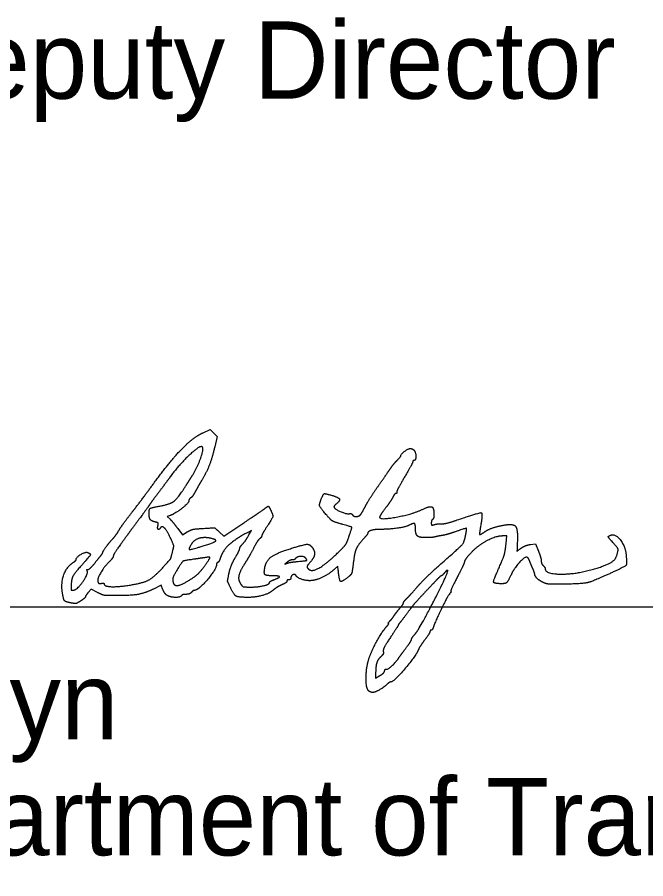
# Model space of a CAD drawing. Extents: x 0 to 34, y 0 to 22.
# Drawn here: x 25.68 to 26.819, y 7.064 to 8.624 of the extents above; entities that cross this region are included whole.
import ezdxf

# ---------------------------------------------------------------- set-up
doc = ezdxf.new("R2010")
doc.units = 0
for name, color, linetype in [('Default', 7, 'Continuous'), ('SH_Data', 7, 'Continuous'), ('SH_Text', 7, 'Continuous')]:
    doc.layers.add(name, color=color, linetype=linetype)

msp = doc.modelspace()

# ---------------------------------------------------------------- linework, layer by layer
at = {"layer": 'Default'}
for points in [[(26.0172, 7.8718), (26.0299, 7.8777), (26.0362, 7.8713), (26.0426, 7.865), (26.0382, 7.8463)], [(25.9573, 7.7219), (25.9523, 7.7203), (25.9575, 7.7151)], [(26.0463, 7.6922), (26.0544, 7.6846), (26.0907, 7.7087)], [(25.9711, 7.6985), (25.9797, 7.687), (25.9885, 7.6922)], [(26.1002, 7.6869), (26.1046, 7.6949), (26.0991, 7.6919)], [(26.566, 7.671), (26.5675, 7.6848), (26.5597, 7.6848)], [(26.6099, 7.6694), (26.6195, 7.6709), (26.6246, 7.6574)], [(26.2619, 7.6232), (26.2613, 7.63), (26.2554, 7.6249)], [(25.9443, 7.5876), (25.941, 7.5956), (25.9271, 7.5888)], [(25.8257, 7.5826), (25.8142, 7.5884), (25.8091, 7.5826)], [(26.3297, 7.4371), (26.3297, 7.4277), (26.3372, 7.4321)]]:
    msp.add_lwpolyline(points, dxfattribs=at)
for points in [[(25.9277, 7.78), (25.9574, 7.8206), (25.9992, 7.8635), (26.0172, 7.8718)], [(26.0158, 7.846), (26.0121, 7.8497), (25.9736, 7.814), (25.9582, 7.7927)], [(25.9975, 7.794), (26.0069, 7.8089), (26.0189, 7.8429), (26.0158, 7.846)], [(26.0382, 7.8463), (26.0332, 7.8251), (26.024, 7.8015), (26.0146, 7.7856)], [(26.3753, 7.8299), (26.3753, 7.8327), (26.3885, 7.843), (26.3922, 7.8431)], [(26.3922, 7.8431), (26.3942, 7.8432), (26.3972, 7.8419), (26.3988, 7.8403)], [(26.3687, 7.8218), (26.3723, 7.8254), (26.3753, 7.8291), (26.3753, 7.8299)], [(26.3988, 7.8403), (26.4023, 7.8368), (26.4027, 7.8216), (26.3993, 7.8216)], [(26.3549, 7.8046), (26.3588, 7.8104), (26.3651, 7.8182), (26.3687, 7.8218)], [(26.3969, 7.8191), (26.3969, 7.8177), (26.3904, 7.8056), (26.3825, 7.7922)], [(26.3993, 7.8216), (26.398, 7.8216), (26.3969, 7.8205), (26.3969, 7.8191)], [(26.3333, 7.7736), (26.3412, 7.7848), (26.3509, 7.7988), (26.3549, 7.8046)], [(25.9582, 7.7927), (25.9546, 7.7877), (25.9452, 7.7751), (25.9373, 7.7646)], [(25.987, 7.7773), (25.9902, 7.7825), (25.995, 7.79), (25.9975, 7.794)], [(26.0146, 7.7856), (26.0111, 7.7797), (26.0059, 7.7705), (26.003, 7.7652)], [(26.3825, 7.7922), (26.3746, 7.7788), (26.3681, 7.7664), (26.3681, 7.7647)], [(25.8875, 7.7265), (25.8964, 7.7379), (25.9145, 7.7619), (25.9277, 7.78)], [(25.9372, 7.7387), (25.9578, 7.7424), (25.9718, 7.7533), (25.987, 7.7773)], [(26.003, 7.7652), (26.0002, 7.7599), (25.9964, 7.7547), (25.9946, 7.7537)], [(26.3119, 7.74), (26.3157, 7.7473), (26.3253, 7.7624), (26.3333, 7.7736)], [(25.9373, 7.7646), (25.9294, 7.7541), (25.9213, 7.7431), (25.9193, 7.7401)], [(25.9946, 7.7537), (25.9928, 7.7526), (25.9913, 7.7502), (25.9913, 7.7483)], [(26.241, 7.7224), (26.2295, 7.7355), (26.2273, 7.7423), (26.2312, 7.7519)], [(26.2312, 7.7519), (26.235, 7.7609), (26.2381, 7.7619), (26.2508, 7.7582)], [(26.2508, 7.7582), (26.2628, 7.7546), (26.2657, 7.7484), (26.258, 7.7426)], [(26.3608, 7.755), (26.359, 7.7514), (26.3529, 7.7423), (26.3472, 7.7348)], [(26.3661, 7.7616), (26.365, 7.7616), (26.3626, 7.7586), (26.3608, 7.755)], [(26.3681, 7.7647), (26.3681, 7.763), (26.3672, 7.7616), (26.3661, 7.7616)], [(25.9193, 7.7401), (25.9173, 7.7372), (25.9019, 7.7162), (25.8851, 7.6936)], [(25.9193, 7.7265), (25.9193, 7.7334), (25.9234, 7.7362), (25.9372, 7.7387)], [(25.9913, 7.7483), (25.9913, 7.7445), (25.9655, 7.7245), (25.9573, 7.7219)], [(26.0907, 7.7087), (26.1106, 7.7219), (26.1282, 7.7339), (26.1298, 7.7352)], [(26.1298, 7.7352), (26.1343, 7.739), (26.1367, 7.7381), (26.1397, 7.7315)], [(26.258, 7.7426), (26.2553, 7.7405), (26.2538, 7.7377), (26.2547, 7.7363)], [(26.2547, 7.7363), (26.2574, 7.7325), (26.2773, 7.7243), (26.2819, 7.7251)], [(26.3026, 7.7238), (26.3039, 7.7254), (26.3081, 7.7327), (26.3119, 7.74)], [(26.3472, 7.7348), (26.3415, 7.7273), (26.3369, 7.7201), (26.3369, 7.7187)], [(26.4145, 7.733), (26.4274, 7.7391), (26.4353, 7.736), (26.4353, 7.7246)], [(25.866, 7.6971), (25.8689, 7.702), (25.8786, 7.7152), (25.8875, 7.7265)], [(25.9303, 7.7102), (25.9231, 7.712), (25.9193, 7.7177), (25.9193, 7.7265)], [(26.1397, 7.7315), (26.1441, 7.7219), (26.1431, 7.7177), (26.1329, 7.7019)], [(26.2645, 7.7073), (26.2537, 7.7104), (26.2488, 7.7136), (26.241, 7.7224)], [(26.2819, 7.7251), (26.2842, 7.7255), (26.2868, 7.7247), (26.2876, 7.7233)], [(26.2876, 7.7233), (26.2898, 7.7198), (26.2998, 7.7201), (26.3026, 7.7238)], [(26.3369, 7.7187), (26.3369, 7.7134), (26.3965, 7.7244), (26.4145, 7.733)], [(26.4353, 7.7246), (26.4353, 7.72), (26.4342, 7.7156), (26.4329, 7.7148)], [(26.4776, 7.7139), (26.518, 7.7278), (26.5239, 7.7261), (26.5198, 7.7022)], [(25.9354, 7.7039), (25.9363, 7.7074), (25.9351, 7.709), (25.9303, 7.7102)], [(25.9396, 7.6991), (25.9372, 7.6952), (25.934, 7.6988), (25.9354, 7.7039)], [(25.9575, 7.7151), (25.9603, 7.7123), (25.9664, 7.7048), (25.9711, 7.6985)], [(26.2813, 7.6835), (26.2869, 7.7004), (26.2866, 7.7009), (26.2645, 7.7073)], [(26.3902, 7.7042), (26.3847, 7.7012), (26.3545, 7.6968), (26.3395, 7.6968)], [(26.4017, 7.6995), (26.4017, 7.7068), (26.398, 7.7083), (26.3902, 7.7042)], [(26.4329, 7.7148), (26.4316, 7.714), (26.4305, 7.7111), (26.4305, 7.7085)], [(26.4305, 7.7085), (26.4305, 7.7046), (26.4315, 7.704), (26.4359, 7.7054)], [(26.4359, 7.7054), (26.4389, 7.7063), (26.4447, 7.707), (26.4488, 7.7068)], [(26.4488, 7.7068), (26.453, 7.7067), (26.4659, 7.7098), (26.4776, 7.7139)], [(26.5257, 7.6914), (26.533, 7.6965), (26.5512, 7.7028), (26.5649, 7.7049)], [(26.5649, 7.7049), (26.5795, 7.7072), (26.5872, 7.6968), (26.5864, 7.6756)], [(25.8497, 7.6753), (25.8563, 7.6826), (25.8605, 7.6883), (25.866, 7.6971)], [(25.8851, 7.6936), (25.8684, 7.6709), (25.8546, 7.6508), (25.8545, 7.6488)], [(25.9584, 7.6805), (25.9523, 7.6942), (25.9426, 7.7039), (25.9396, 7.6991)], [(25.9885, 7.6922), (25.995, 7.6961), (26.0026, 7.6977), (26.0177, 7.6986)], [(26.0177, 7.6986), (26.038, 7.6998), (26.0382, 7.6997), (26.0463, 7.6922)], [(26.0991, 7.6919), (26.0757, 7.6794), (26.0529, 7.6587), (26.0488, 7.6462)], [(26.1329, 7.7019), (26.1276, 7.6937), (26.1233, 7.6861), (26.1233, 7.685)], [(26.3153, 7.6896), (26.3153, 7.6887), (26.3111, 7.6833), (26.3059, 7.6776)], [(26.3395, 7.6968), (26.328, 7.6968), (26.3153, 7.693), (26.3153, 7.6896)], [(26.421, 7.6818), (26.4086, 7.6818), (26.4017, 7.6881), (26.4017, 7.6995)], [(26.448, 7.6343), (26.4836, 7.6658), (26.4905, 7.674), (26.4929, 7.6873)], [(26.4723, 7.6919), (26.4645, 7.6892), (26.4548, 7.6865), (26.4509, 7.6858)], [(26.4929, 7.6873), (26.495, 7.6988), (26.4932, 7.6991), (26.4723, 7.6919)], [(26.5198, 7.7022), (26.5184, 7.6946), (26.5177, 7.688), (26.5182, 7.6875)], [(26.5182, 7.6875), (26.5186, 7.6871), (26.522, 7.6888), (26.5257, 7.6914)], [(25.8353, 7.6548), (25.8353, 7.6564), (25.8444, 7.6694), (25.8497, 7.6753)], [(25.9617, 7.656), (25.9643, 7.6658), (25.964, 7.668), (25.9584, 7.6805)], [(26.0295, 7.6809), (26.0186, 7.683), (26.0012, 7.678), (25.9969, 7.6714)], [(26.0189, 7.6673), (26.0381, 7.6733), (26.0421, 7.6783), (26.0295, 7.6809)], [(26.0874, 7.6688), (26.0928, 7.6748), (26.0953, 7.6783), (26.1002, 7.6869)], [(26.1197, 7.68), (26.1178, 7.6784), (26.1147, 7.6742), (26.1128, 7.6707)], [(26.1233, 7.685), (26.1233, 7.6839), (26.1217, 7.6817), (26.1197, 7.68)], [(26.263, 7.6562), (26.2734, 7.6663), (26.2775, 7.6724), (26.2813, 7.6835)], [(26.3059, 7.6776), (26.2974, 7.6681), (26.2917, 7.6555), (26.2901, 7.6428)], [(26.4377, 7.6832), (26.4344, 7.6824), (26.4269, 7.6818), (26.421, 7.6818)], [(26.4509, 7.6858), (26.4469, 7.6852), (26.441, 7.684), (26.4377, 7.6832)], [(26.5597, 7.6848), (26.547, 7.6848), (26.5132, 7.6664), (26.501, 7.6528)], [(26.5864, 7.6756), (26.5857, 7.6572), (26.5856, 7.6574), (26.5933, 7.6629)], [(26.7565, 7.6762), (26.7512, 7.6819), (26.7509, 7.6845), (26.7556, 7.6863)], [(26.7556, 7.6863), (26.7641, 7.6896), (26.7826, 7.6646), (26.7836, 7.6484)], [(26.7656, 7.6471), (26.7696, 7.6589), (26.768, 7.6638), (26.7565, 7.6762)], [(25.9421, 7.6255), (25.9582, 7.6431), (25.9585, 7.6436), (25.9617, 7.656)], [(25.9969, 7.6714), (25.9899, 7.6606), (25.9944, 7.6598), (26.0189, 7.6673)], [(26.0749, 7.6447), (26.0793, 7.6523), (26.0831, 7.66), (26.0834, 7.6617)], [(26.0834, 7.6617), (26.0837, 7.6635), (26.0854, 7.6667), (26.0874, 7.6688)], [(26.1128, 7.6707), (26.1047, 7.6553), (26.0969, 7.6416), (26.0908, 7.6319)], [(26.129, 7.628), (26.1312, 7.6393), (26.1474, 7.6526), (26.1667, 7.659)], [(26.1667, 7.659), (26.1985, 7.6696), (26.2119, 7.6701), (26.217, 7.6606)], [(26.206, 7.6274), (26.2113, 7.6187), (26.238, 7.6322), (26.263, 7.6562)], [(26.217, 7.6606), (26.2202, 7.6546), (26.2168, 7.6432), (26.2094, 7.6353)], [(26.5513, 7.6231), (26.5604, 7.6431), (26.5644, 7.6562), (26.566, 7.671)], [(26.5933, 7.6629), (26.5971, 7.6656), (26.6045, 7.6685), (26.6099, 7.6694)], [(26.6246, 7.6574), (26.6274, 7.6499), (26.6297, 7.6418), (26.6297, 7.6393)], [(25.7826, 7.6374), (25.7852, 7.639), (25.7873, 7.6414), (25.7873, 7.6428)], [(25.7873, 7.6428), (25.7874, 7.6465), (25.8041, 7.6565), (25.8079, 7.655)], [(25.8079, 7.655), (25.8139, 7.6528), (25.8116, 7.6479), (25.7973, 7.632)], [(25.8208, 7.6356), (25.8261, 7.6422), (25.8316, 7.6489), (25.8329, 7.6505)], [(25.8329, 7.6505), (25.8342, 7.6521), (25.8353, 7.654), (25.8353, 7.6548)], [(25.8545, 7.6488), (25.8544, 7.6468), (25.8511, 7.642), (25.8471, 7.6381)], [(25.9997, 7.6426), (25.9819, 7.64), (25.9799, 7.6388), (25.9726, 7.6276)], [(26.0171, 7.6452), (26.0115, 7.6443), (26.0036, 7.6431), (25.9997, 7.6426)], [(26.0221, 7.6336), (26.0299, 7.6449), (26.029, 7.6471), (26.0171, 7.6452)], [(26.0488, 7.6462), (26.0471, 7.641), (26.0448, 7.6368), (26.0437, 7.6368)], [(26.064, 7.6168), (26.0656, 7.6245), (26.0705, 7.637), (26.0749, 7.6447)], [(26.1788, 7.6416), (26.1765, 7.6416), (26.1725, 7.6399), (26.1699, 7.6378)], [(26.1843, 7.6437), (26.1836, 7.6425), (26.1811, 7.6416), (26.1788, 7.6416)], [(26.2028, 7.6448), (26.2, 7.6482), (26.1866, 7.6474), (26.1843, 7.6437)], [(26.1869, 7.6385), (26.2036, 7.64), (26.206, 7.6409), (26.2028, 7.6448)], [(26.2901, 7.6428), (26.2873, 7.6203), (26.2855, 7.6148), (26.2799, 7.6103)], [(26.501, 7.6528), (26.4952, 7.6464), (26.4905, 7.6398), (26.4905, 7.6382)], [(26.6029, 7.6464), (26.5986, 7.6464), (26.5803, 7.6259), (26.5756, 7.6157)], [(26.6085, 7.6398), (26.607, 7.6434), (26.6045, 7.6464), (26.6029, 7.6464)], [(26.7167, 7.6228), (26.7404, 7.629), (26.7634, 7.6404), (26.7656, 7.6471)], [(26.7836, 7.6484), (26.7845, 7.633), (26.7819, 7.6299), (26.7585, 7.6189)], [(25.7624, 7.5811), (25.7595, 7.5997), (25.7702, 7.6297), (25.7826, 7.6374)], [(25.7973, 7.632), (25.7836, 7.6168), (25.7786, 7.6067), (25.778, 7.5928)], [(25.8085, 7.6243), (25.8099, 7.6239), (25.8154, 7.629), (25.8208, 7.6356)], [(25.8471, 7.6381), (25.8373, 7.6284), (25.8249, 7.6063), (25.8267, 7.6016)], [(25.8856, 7.5961), (25.9083, 7.5998), (25.9279, 7.61), (25.9421, 7.6255)], [(25.9726, 7.6276), (25.9644, 7.615), (25.9612, 7.6051), (25.9634, 7.5993)], [(25.9922, 7.6049), (26.0034, 7.6118), (26.0143, 7.6224), (26.0221, 7.6336)], [(26.0416, 7.6338), (26.0415, 7.6253), (26.0084, 7.5864), (26.0013, 7.5864)], [(26.0437, 7.6368), (26.0426, 7.6368), (26.0417, 7.6354), (26.0416, 7.6338)], [(26.0908, 7.6319), (26.0828, 7.6192), (26.0806, 7.604), (26.0857, 7.5972)], [(26.1426, 7.6128), (26.1311, 7.6128), (26.127, 7.6173), (26.129, 7.628)], [(26.1699, 7.6378), (26.1653, 7.6341), (26.1653, 7.634), (26.1701, 7.6357)], [(26.1701, 7.6357), (26.1727, 7.6366), (26.1803, 7.6379), (26.1869, 7.6385)], [(26.2094, 7.6353), (26.2066, 7.6323), (26.2051, 7.6288), (26.206, 7.6274)], [(26.2554, 7.6249), (26.246, 7.6167), (26.226, 7.6061), (26.2169, 7.6045)], [(26.404, 7.5915), (26.4112, 7.5999), (26.431, 7.6192), (26.448, 7.6343)], [(26.4905, 7.6382), (26.4905, 7.6366), (26.4845, 7.6238), (26.4773, 7.6097)], [(26.6144, 7.6256), (26.6126, 7.6298), (26.6099, 7.6362), (26.6085, 7.6398)], [(26.6178, 7.616), (26.6177, 7.6171), (26.6162, 7.6215), (26.6144, 7.6256)], [(26.6297, 7.6393), (26.6297, 7.6368), (26.6313, 7.6331), (26.6333, 7.6311)], [(26.6333, 7.6311), (26.6353, 7.6292), (26.6369, 7.6265), (26.6369, 7.6251)], [(26.6369, 7.6251), (26.6369, 7.6166), (26.6875, 7.6151), (26.7167, 7.6228)], [(25.7828, 7.5868), (25.7892, 7.5878), (25.8093, 7.6162), (25.8073, 7.6214)], [(25.8073, 7.6214), (25.8065, 7.6234), (25.8071, 7.6247), (25.8085, 7.6243)], [(26.066, 7.5928), (26.0616, 7.6019), (26.0614, 7.6041), (26.064, 7.6168)], [(26.146, 7.6059), (26.1563, 7.6096), (26.1547, 7.6128), (26.1426, 7.6128)], [(26.1856, 7.6129), (26.1836, 7.6162), (26.1761, 7.6131), (26.1761, 7.6089)], [(26.2169, 7.6045), (26.2083, 7.6029), (26.1885, 7.6083), (26.1856, 7.6129)], [(26.2799, 7.6103), (26.2681, 7.6011), (26.2638, 7.6043), (26.2619, 7.6232)], [(26.4014, 7.5077), (26.409, 7.5164), (26.4623, 7.6202), (26.4602, 7.6223)], [(26.4487, 7.6128), (26.4479, 7.6128), (26.444, 7.6093), (26.4399, 7.605)], [(26.4545, 7.6182), (26.4521, 7.6152), (26.4495, 7.6128), (26.4487, 7.6128)], [(26.4602, 7.6223), (26.4595, 7.623), (26.4569, 7.6212), (26.4545, 7.6182)], [(26.4773, 7.6097), (26.47, 7.5955), (26.4648, 7.584), (26.4659, 7.584)], [(26.5587, 7.5984), (26.5442, 7.5984), (26.5426, 7.6038), (26.5513, 7.6231)], [(26.5756, 7.6157), (26.5699, 7.6033), (26.565, 7.5984), (26.5587, 7.5984)], [(26.6334, 7.6005), (26.6264, 7.6038), (26.6179, 7.6122), (26.6178, 7.616)], [(26.7585, 7.6189), (26.7237, 7.6026), (26.7027, 7.5979), (26.6633, 7.5974)], [(25.8267, 7.6016), (25.8276, 7.5993), (25.8299, 7.5983), (25.8329, 7.5991)], [(25.8329, 7.5991), (25.8355, 7.5998), (25.8377, 7.5994), (25.8377, 7.5983)], [(25.8377, 7.5983), (25.8377, 7.5937), (25.8633, 7.5925), (25.8856, 7.5961)], [(25.9634, 7.5993), (25.9655, 7.5941), (25.979, 7.5967), (25.9922, 7.6049)], [(26.0857, 7.5972), (26.0885, 7.5934), (26.0921, 7.5924), (26.1033, 7.5924)], [(26.1033, 7.5924), (26.1173, 7.5924), (26.1377, 7.5975), (26.1377, 7.601)], [(26.1377, 7.601), (26.1377, 7.602), (26.1414, 7.6042), (26.146, 7.6059)], [(26.1635, 7.5982), (26.1561, 7.5949), (26.1485, 7.5904), (26.1443, 7.5869)], [(26.1689, 7.6031), (26.1689, 7.6018), (26.1665, 7.5996), (26.1635, 7.5982)], [(26.1725, 7.6056), (26.1705, 7.6056), (26.1689, 7.6045), (26.1689, 7.6031)], [(26.1761, 7.6089), (26.1761, 7.6071), (26.1745, 7.6056), (26.1725, 7.6056)], [(26.4399, 7.605), (26.4358, 7.6007), (26.4253, 7.5896), (26.4165, 7.5803)], [(26.6633, 7.5974), (26.6483, 7.5972), (26.638, 7.5983), (26.6334, 7.6005)], [(25.779, 7.5634), (25.7681, 7.5655), (25.7643, 7.5695), (25.7624, 7.5811)], [(25.778, 7.5928), (25.7778, 7.5872), (25.7786, 7.5862), (25.7828, 7.5868)], [(25.8091, 7.5826), (25.8063, 7.5794), (25.8041, 7.576), (25.8041, 7.575)], [(25.8565, 7.5768), (25.8409, 7.5768), (25.835, 7.5779), (25.8257, 7.5826)], [(25.9271, 7.5888), (25.9115, 7.5811), (25.8864, 7.5768), (25.8565, 7.5768)], [(25.9525, 7.577), (25.9499, 7.5784), (25.9462, 7.5832), (25.9443, 7.5876)], [(25.9863, 7.5792), (25.9826, 7.5792), (25.9789, 7.5781), (25.9781, 7.5768)], [(25.9961, 7.5828), (25.9944, 7.5808), (25.99, 7.5792), (25.9863, 7.5792)], [(26.0013, 7.5864), (26.0001, 7.5864), (25.9977, 7.5848), (25.9961, 7.5828)], [(26.0978, 7.5737), (26.0803, 7.5738), (26.0733, 7.578), (26.066, 7.5928)], [(26.1443, 7.5869), (26.1366, 7.5805), (26.1123, 7.5736), (26.0978, 7.5737)], [(26.3855, 7.5711), (26.3885, 7.574), (26.3968, 7.5831), (26.404, 7.5915)], [(26.4165, 7.5803), (26.4077, 7.5711), (26.3978, 7.5598), (26.3945, 7.5554)], [(26.4651, 7.5822), (26.4624, 7.5803), (26.4372, 7.5293), (26.4342, 7.5198)], [(26.4659, 7.584), (26.4669, 7.5839), (26.4665, 7.5831), (26.4651, 7.5822)], [(25.7957, 7.5675), (25.7892, 7.5631), (25.7856, 7.5622), (25.779, 7.5634)], [(25.8041, 7.575), (25.8041, 7.574), (25.8003, 7.5706), (25.7957, 7.5675)], [(25.9781, 7.5768), (25.9761, 7.5736), (25.9586, 7.5737), (25.9525, 7.577)], [(26.3735, 7.5541), (26.3771, 7.5583), (26.3801, 7.5628), (26.3801, 7.5639)], [(26.3801, 7.5639), (26.3801, 7.5651), (26.3826, 7.5683), (26.3855, 7.5711)], [(26.3633, 7.5408), (26.3653, 7.5438), (26.3699, 7.5498), (26.3735, 7.5541)], [(26.3945, 7.5554), (26.3864, 7.5444), (26.3759, 7.5306), (26.3729, 7.5271)], [(26.3555, 7.5308), (26.3578, 7.5332), (26.3613, 7.5377), (26.3633, 7.5408)], [(26.3195, 7.4684), (26.3254, 7.4832), (26.3425, 7.5131), (26.3496, 7.521)], [(26.3496, 7.521), (26.3523, 7.524), (26.3538, 7.5264), (26.3529, 7.5264)], [(26.3529, 7.5264), (26.352, 7.5264), (26.3532, 7.5284), (26.3555, 7.5308)], [(26.3705, 7.5232), (26.3705, 7.5227), (26.3642, 7.5127), (26.3564, 7.5011)], [(26.3729, 7.5271), (26.3716, 7.5255), (26.3705, 7.5237), (26.3705, 7.5232)], [(26.4342, 7.5198), (26.4333, 7.5168), (26.4316, 7.5144), (26.4303, 7.5144)], [(26.3564, 7.5011), (26.3477, 7.4881), (26.3428, 7.4783), (26.3435, 7.4756)], [(26.3945, 7.4974), (26.3945, 7.4987), (26.3976, 7.5034), (26.4014, 7.5077)], [(26.4281, 7.5119), (26.4281, 7.5105), (26.4238, 7.5037), (26.4186, 7.4968)], [(26.4303, 7.5144), (26.4291, 7.5144), (26.4281, 7.5133), (26.4281, 7.5119)], [(26.3843, 7.4816), (26.3899, 7.489), (26.3945, 7.4961), (26.3945, 7.4974)], [(26.4186, 7.4968), (26.4134, 7.4899), (26.4083, 7.482), (26.4072, 7.4791)], [(26.3435, 7.4756), (26.3441, 7.4731), (26.3426, 7.4694), (26.3398, 7.467)], [(26.4072, 7.4791), (26.4035, 7.4693), (26.3624, 7.4208), (26.3577, 7.4208)], [(26.3717, 7.4643), (26.373, 7.4664), (26.3787, 7.4742), (26.3843, 7.4816)], [(26.3177, 7.4039), (26.3117, 7.4077), (26.313, 7.452), (26.3195, 7.4684)], [(26.3398, 7.467), (26.3339, 7.4618), (26.3297, 7.4494), (26.3297, 7.4371)], [(26.3489, 7.4436), (26.3508, 7.4424), (26.3674, 7.4575), (26.3717, 7.4643)], [(26.3372, 7.4321), (26.3414, 7.4344), (26.3453, 7.4383), (26.3459, 7.4406)], [(26.3459, 7.4406), (26.3465, 7.4429), (26.3479, 7.4442), (26.3489, 7.4436)], [(26.3502, 7.4162), (26.344, 7.4105), (26.3281, 7.4016), (26.3242, 7.4016)], [(26.3577, 7.4208), (26.3563, 7.4208), (26.353, 7.4187), (26.3502, 7.4162)], [(26.3242, 7.4016), (26.3226, 7.4016), (26.3197, 7.4027), (26.3177, 7.4039)]]:
    msp.add_open_spline(points, degree=2, dxfattribs=at)
at = {"layer": 'SH_Data'}
msp.add_line((24.532, 7.5567), (28.032, 7.5567), dxfattribs=at)

# ---------------------------------------------------------------- texts
at = {"layer": 'SH_Text'}
for s, p in [('District       Deputy Director', (24.5279, 8.4762)), ('Pamela Boratyn', (24.532, 7.3167)), ('Director, Department of Transportation', (24.532, 7.1067))]:
    msp.add_text(s, height=0.14, dxfattribs=at).set_placement(p)

doc.saveas('drawing.dxf')
